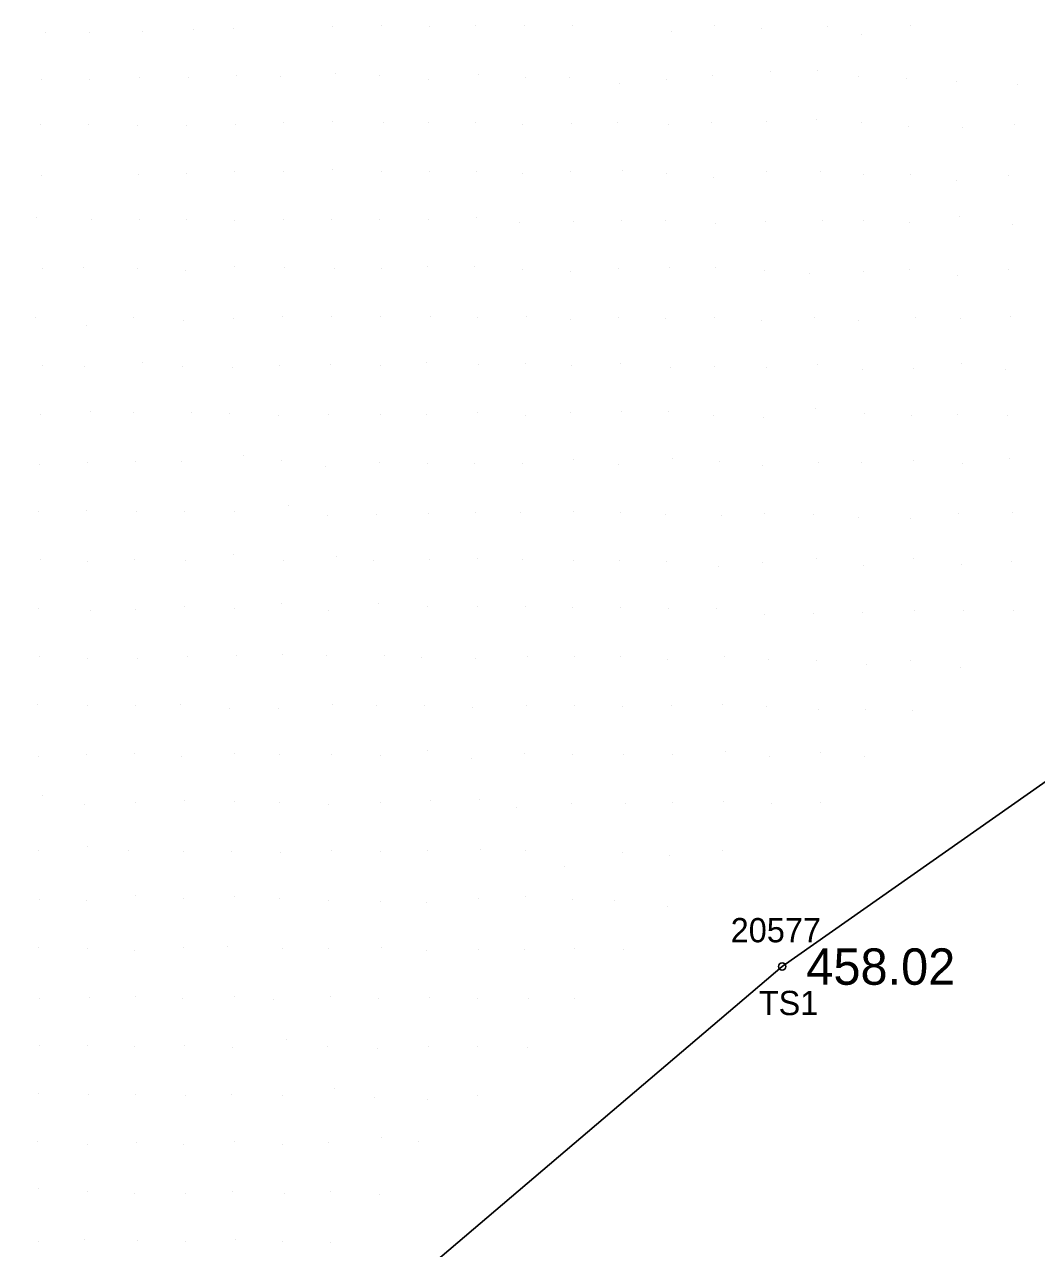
# Model space of a CAD drawing. Extents: x 1747760 to 1751131, y 649333 to 653784.
# Drawn here: x 1749239.9 to 1749281.6, y 651279.3 to 651329.8 of the extents above; entities that cross this region are included whole.
import ezdxf

# ---------------------------------------------------------------- set-up
doc = ezdxf.new("R2010")
doc.units = 0
for name, color, linetype in [('RD_DTM_BkLn2', 7, 'Continuous'), ('RD_DTM_BkLn_txCode', 7, 'Continuous'), ('RD_DTM_Spot', 7, 'Continuous'), ('RD_EX_TX_Misc_ELEV', 7, 'Continuous'), ('RD_SMD_Locator', 7, 'Continuous')]:
    doc.layers.add(name, color=color, linetype=linetype)

msp = doc.modelspace()

# ---------------------------------------------------------------- linework, layer by layer
at = {"layer": 'RD_DTM_BkLn2'}
msp.add_lwpolyline([(1749334.274, 651347.939), (1749311.737, 651326.42), (1749292.613, 651306.019), (1749271.131, 651290.935), (1749254.537, 651276.811), (1749242.73, 651265.483), (1749232.71, 651251.743), (1749211.561, 651228.743), (1749190.496, 651216.053), (1749178.766, 651203.369)], dxfattribs=at)
at = {"layer": 'RD_DTM_Spot'}
for p, q in [((1749240.766, 651329.413), (1749240.766, 651329.413)), ((1749242.609, 651329.431), (1749242.609, 651329.431)), ((1749244.794, 651329.464), (1749244.794, 651329.464)), ((1749246.872, 651329.565), (1749246.872, 651329.565)), ((1749248.519, 651329.588), (1749248.519, 651329.588)), ((1749252.618, 651329.682), (1749252.618, 651329.682)), ((1749254.619, 651329.723), (1749254.619, 651329.723)), ((1749256.621, 651329.689), (1749256.621, 651329.689)), ((1749258.503, 651329.72), (1749258.503, 651329.72)), ((1749260.497, 651329.72), (1749260.497, 651329.72)), ((1749262.483, 651329.693), (1749262.483, 651329.693)), ((1749266.57, 651329.475), (1749266.57, 651329.475)), ((1749268.354, 651329.698), (1749268.354, 651329.698)), ((1749270.294, 651329.598), (1749270.294, 651329.598)), ((1749272.982, 651329.689), (1749272.982, 651329.689)), ((1749274.385, 651329.34), (1749274.385, 651329.34)), ((1749276.403, 651329.729), (1749276.403, 651329.729)), ((1749270.671, 651327.81), (1749270.671, 651327.81)), ((1749272.605, 651327.87), (1749272.605, 651327.87)), ((1749240.602, 651327.495), (1749240.602, 651327.495)), ((1749242.58, 651327.499), (1749242.58, 651327.499)), ((1749244.656, 651327.566), (1749244.656, 651327.566)), ((1749246.659, 651327.567), (1749246.659, 651327.567)), ((1749248.641, 651327.67), (1749248.641, 651327.67)), ((1749250.449, 651327.615), (1749250.449, 651327.615)), ((1749252.719, 651327.722), (1749252.719, 651327.722)), ((1749254.526, 651327.647), (1749254.526, 651327.647)), ((1749256.543, 651327.488), (1749256.543, 651327.488)), ((1749258.629, 651327.674), (1749258.629, 651327.674)), ((1749260.576, 651327.551), (1749260.576, 651327.551)), ((1749262.355, 651327.585), (1749262.355, 651327.585)), ((1749264.438, 651327.329), (1749264.438, 651327.329)), ((1749266.363, 651327.489), (1749266.363, 651327.489)), ((1749268.274, 651327.663), (1749268.274, 651327.663)), ((1749274.26, 651327.61), (1749274.26, 651327.61)), ((1749276.263, 651327.527), (1749276.263, 651327.527)), ((1749278.316, 651327.392), (1749278.316, 651327.392)), ((1749280.846, 651327.27), (1749280.846, 651327.27)), ((1749272.541, 651325.844), (1749272.541, 651325.844)), ((1749240.562, 651325.637), (1749240.562, 651325.637)), ((1749242.548, 651325.621), (1749242.548, 651325.621)), ((1749244.556, 651325.61), (1749244.556, 651325.61)), ((1749246.572, 651325.599), (1749246.572, 651325.599)), ((1749248.597, 651325.652), (1749248.597, 651325.652)), ((1749250.574, 651325.699), (1749250.574, 651325.699)), ((1749252.592, 651325.768), (1749252.592, 651325.768)), ((1749254.706, 651325.723), (1749254.706, 651325.723)), ((1749256.564, 651325.721), (1749256.564, 651325.721)), ((1749258.508, 651325.718), (1749258.508, 651325.718)), ((1749260.428, 651325.646), (1749260.428, 651325.646)), ((1749262.458, 651325.678), (1749262.458, 651325.678)), ((1749264.338, 651325.709), (1749264.338, 651325.709)), ((1749266.43, 651325.651), (1749266.43, 651325.651)), ((1749268.219, 651325.729), (1749268.219, 651325.729)), ((1749270.497, 651325.769), (1749270.497, 651325.769)), ((1749274.394, 651325.717), (1749274.394, 651325.717)), ((1749276.338, 651325.557), (1749276.338, 651325.557)), ((1749278.566, 651325.527), (1749278.566, 651325.527)), ((1749280.727, 651325.625), (1749280.727, 651325.625)), ((1749252.606, 651323.773), (1749252.606, 651323.773)), ((1749240.626, 651323.519), (1749240.626, 651323.519)), ((1749244.602, 651323.587), (1749244.602, 651323.587)), ((1749246.601, 651323.595), (1749246.601, 651323.595)), ((1749248.581, 651323.68), (1749248.581, 651323.68)), ((1749250.587, 651323.713), (1749250.587, 651323.713)), ((1749254.608, 651323.712), (1749254.608, 651323.712)), ((1749256.604, 651323.678), (1749256.604, 651323.678)), ((1749258.531, 651323.677), (1749258.531, 651323.677)), ((1749260.439, 651323.609), (1749260.439, 651323.609)), ((1749262.406, 651323.688), (1749262.406, 651323.688)), ((1749264.575, 651323.756), (1749264.575, 651323.756)), ((1749266.376, 651323.596), (1749266.376, 651323.596)), ((1749268.302, 651323.45), (1749268.302, 651323.45)), ((1749270.487, 651323.704), (1749270.487, 651323.704)), ((1749272.727, 651323.695), (1749272.727, 651323.695)), ((1749274.499, 651323.573), (1749274.499, 651323.573)), ((1749276.429, 651323.591), (1749276.429, 651323.591)), ((1749278.321, 651323.307), (1749278.321, 651323.307)), ((1749280.453, 651323.546), (1749280.453, 651323.546)), ((1749240.397, 651321.808), (1749240.397, 651321.808)), ((1749258.531, 651321.803), (1749258.531, 651321.803)), ((1749278.439, 651321.853), (1749278.439, 651321.853)), ((1749242.686, 651321.703), (1749242.686, 651321.703)), ((1749244.642, 651321.707), (1749244.642, 651321.707)), ((1749246.604, 651321.72), (1749246.604, 651321.72)), ((1749248.569, 651321.683), (1749248.569, 651321.683)), ((1749250.567, 651321.708), (1749250.567, 651321.708)), ((1749252.582, 651321.699), (1749252.582, 651321.699)), ((1749254.531, 651321.733), (1749254.531, 651321.733)), ((1749256.579, 651321.727), (1749256.579, 651321.727)), ((1749260.31, 651321.613), (1749260.31, 651321.613)), ((1749262.516, 651321.619), (1749262.516, 651321.619)), ((1749264.526, 651321.667), (1749264.526, 651321.667)), ((1749266.33, 651321.684), (1749266.33, 651321.684)), ((1749268.403, 651321.569), (1749268.403, 651321.569)), ((1749270.431, 651321.639), (1749270.431, 651321.639)), ((1749272.786, 651321.673), (1749272.786, 651321.673)), ((1749274.486, 651321.681), (1749274.486, 651321.681)), ((1749276.388, 651321.614), (1749276.388, 651321.614)), ((1749280.627, 651321.51), (1749280.627, 651321.51)), ((1749242.358, 651319.728), (1749242.358, 651319.728)), ((1749248.565, 651319.764), (1749248.565, 651319.764)), ((1749250.612, 651319.752), (1749250.612, 651319.752)), ((1749256.529, 651319.791), (1749256.529, 651319.791)), ((1749258.466, 651319.787), (1749258.466, 651319.787)), ((1749240.64, 651319.706), (1749240.64, 651319.706)), ((1749244.557, 651319.688), (1749244.557, 651319.688)), ((1749246.548, 651319.634), (1749246.548, 651319.634)), ((1749252.668, 651319.681), (1749252.668, 651319.681)), ((1749254.637, 651319.683), (1749254.637, 651319.683)), ((1749260.428, 651319.663), (1749260.428, 651319.663)), ((1749262.4, 651319.591), (1749262.4, 651319.591)), ((1749264.392, 651319.699), (1749264.392, 651319.699)), ((1749266.491, 651319.722), (1749266.491, 651319.722)), ((1749268.372, 651319.727), (1749268.372, 651319.727)), ((1749270.4, 651319.613), (1749270.4, 651319.613)), ((1749272.261, 651319.493), (1749272.261, 651319.493)), ((1749274.49, 651319.564), (1749274.49, 651319.564)), ((1749276.375, 651319.647), (1749276.375, 651319.647)), ((1749278.35, 651319.432), (1749278.35, 651319.432)), ((1749280.469, 651319.661), (1749280.469, 651319.661)), ((1749252.557, 651317.736), (1749252.557, 651317.736)), ((1749254.592, 651317.723), (1749254.592, 651317.723)), ((1749260.611, 651317.715), (1749260.611, 651317.715)), ((1749240.356, 651317.687), (1749240.356, 651317.687)), ((1749242.464, 651317.346), (1749242.464, 651317.346)), ((1749244.399, 651317.69), (1749244.399, 651317.69)), ((1749246.475, 651317.553), (1749246.475, 651317.553)), ((1749248.528, 651317.622), (1749248.528, 651317.622)), ((1749250.527, 651317.709), (1749250.527, 651317.709)), ((1749256.629, 651317.705), (1749256.629, 651317.705)), ((1749258.566, 651317.676), (1749258.566, 651317.676)), ((1749262.404, 651317.615), (1749262.404, 651317.615)), ((1749264.398, 651317.696), (1749264.398, 651317.696)), ((1749266.337, 651317.652), (1749266.337, 651317.652)), ((1749268.349, 651317.688), (1749268.349, 651317.688)), ((1749270.281, 651317.571), (1749270.281, 651317.571)), ((1749272.446, 651317.661), (1749272.446, 651317.661)), ((1749274.275, 651317.563), (1749274.275, 651317.563)), ((1749276.646, 651317.662), (1749276.646, 651317.662)), ((1749278.477, 651317.626), (1749278.477, 651317.626)), ((1749280.557, 651317.703), (1749280.557, 651317.703)), ((1749240.66, 651315.712), (1749240.66, 651315.712)), ((1749244.792, 651315.827), (1749244.792, 651315.827)), ((1749250.44, 651315.698), (1749250.44, 651315.698)), ((1749252.512, 651315.744), (1749252.512, 651315.744)), ((1749254.577, 651315.696), (1749254.577, 651315.696)), ((1749256.484, 651315.811), (1749256.484, 651315.811)), ((1749258.639, 651315.732), (1749258.639, 651315.732)), ((1749260.574, 651315.786), (1749260.574, 651315.786)), ((1749262.445, 651315.71), (1749262.445, 651315.71)), ((1749264.453, 651315.769), (1749264.453, 651315.769)), ((1749272.573, 651315.76), (1749272.573, 651315.76)), ((1749278.524, 651315.8), (1749278.524, 651315.8)), ((1749242.374, 651315.681), (1749242.374, 651315.681)), ((1749246.408, 651315.659), (1749246.408, 651315.659)), ((1749248.492, 651315.615), (1749248.492, 651315.615)), ((1749266.549, 651315.604), (1749266.549, 651315.604)), ((1749268.332, 651315.68), (1749268.332, 651315.68)), ((1749270.468, 651315.641), (1749270.468, 651315.641)), ((1749274.457, 651315.557), (1749274.457, 651315.557)), ((1749276.527, 651315.581), (1749276.527, 651315.581)), ((1749280.356, 651315.531), (1749280.356, 651315.531)), ((1749240.565, 651313.692), (1749240.565, 651313.692)), ((1749242.652, 651313.799), (1749242.652, 651313.799)), ((1749244.401, 651313.766), (1749244.401, 651313.766)), ((1749246.814, 651313.783), (1749246.814, 651313.783)), ((1749248.381, 651313.725), (1749248.381, 651313.725)), ((1749254.599, 651313.697), (1749254.599, 651313.697)), ((1749258.583, 651313.748), (1749258.583, 651313.748)), ((1749262.43, 651313.749), (1749262.43, 651313.749)), ((1749264.499, 651313.8), (1749264.499, 651313.8)), ((1749266.43, 651313.804), (1749266.43, 651313.804)), ((1749272.508, 651313.927), (1749272.508, 651313.927)), ((1749274.526, 651313.722), (1749274.526, 651313.722)), ((1749278.346, 651313.699), (1749278.346, 651313.699)), ((1749250.385, 651313.637), (1749250.385, 651313.637)), ((1749252.445, 651313.669), (1749252.445, 651313.669)), ((1749256.483, 651313.673), (1749256.483, 651313.673)), ((1749260.577, 651313.633), (1749260.577, 651313.633)), ((1749268.305, 651313.637), (1749268.305, 651313.637)), ((1749270.373, 651313.567), (1749270.373, 651313.567)), ((1749276.457, 651313.646), (1749276.457, 651313.646)), ((1749280.4, 651313.628), (1749280.4, 651313.628)), ((1749242.5, 651311.721), (1749242.5, 651311.721)), ((1749244.479, 651311.734), (1749244.479, 651311.734)), ((1749246.379, 651311.757), (1749246.379, 651311.757)), ((1749248.941, 651311.981), (1749248.941, 651311.981)), ((1749250.487, 651311.782), (1749250.487, 651311.782)), ((1749254.532, 651311.718), (1749254.532, 651311.718)), ((1749256.502, 651311.668), (1749256.502, 651311.668)), ((1749258.445, 651311.661), (1749258.445, 651311.661)), ((1749262.536, 651311.811), (1749262.536, 651311.811)), ((1749266.617, 651311.867), (1749266.617, 651311.867)), ((1749268.568, 651311.765), (1749268.568, 651311.765)), ((1749272.621, 651311.713), (1749272.621, 651311.713)), ((1749274.421, 651311.703), (1749274.421, 651311.703)), ((1749276.549, 651311.788), (1749276.549, 651311.788)), ((1749278.548, 651311.667), (1749278.548, 651311.667)), ((1749280.515, 651311.851), (1749280.515, 651311.851)), ((1749240.514, 651311.634), (1749240.514, 651311.634)), ((1749252.316, 651311.554), (1749252.316, 651311.554)), ((1749260.454, 651311.645), (1749260.454, 651311.645)), ((1749264.391, 651311.643), (1749264.391, 651311.643)), ((1749270.305, 651311.584), (1749270.305, 651311.584)), ((1749240.472, 651309.675), (1749240.472, 651309.675)), ((1749242.471, 651309.709), (1749242.471, 651309.709)), ((1749244.509, 651309.675), (1749244.509, 651309.675)), ((1749246.521, 651309.705), (1749246.521, 651309.705)), ((1749248.562, 651309.688), (1749248.562, 651309.688)), ((1749250.788, 651309.921), (1749250.788, 651309.921)), ((1749258.511, 651309.66), (1749258.511, 651309.66)), ((1749262.523, 651309.677), (1749262.523, 651309.677)), ((1749264.49, 651309.643), (1749264.49, 651309.643)), ((1749280.63, 651309.659), (1749280.63, 651309.659)), ((1749252.407, 651309.538), (1749252.407, 651309.538)), ((1749254.409, 651309.578), (1749254.409, 651309.578)), ((1749256.56, 651309.619), (1749256.56, 651309.619)), ((1749260.354, 651309.629), (1749260.354, 651309.629)), ((1749266.318, 651309.573), (1749266.318, 651309.573)), ((1749268.623, 651309.525), (1749268.623, 651309.525)), ((1749270.387, 651309.608), (1749270.387, 651309.608)), ((1749272.431, 651309.572), (1749272.431, 651309.572)), ((1749274.272, 651309.431), (1749274.272, 651309.431)), ((1749276.437, 651309.403), (1749276.437, 651309.403)), ((1749278.408, 651309.588), (1749278.408, 651309.588)), ((1749240.559, 651307.713), (1749240.559, 651307.713)), ((1749242.527, 651307.641), (1749242.527, 651307.641)), ((1749244.441, 651307.716), (1749244.441, 651307.716)), ((1749246.528, 651307.655), (1749246.528, 651307.655)), ((1749248.534, 651307.907), (1749248.534, 651307.907)), ((1749250.594, 651307.656), (1749250.594, 651307.656)), ((1749252.755, 651307.822), (1749252.755, 651307.822)), ((1749254.285, 651307.674), (1749254.285, 651307.674)), ((1749256.593, 651307.691), (1749256.593, 651307.691)), ((1749258.564, 651307.732), (1749258.564, 651307.732)), ((1749260.435, 651307.703), (1749260.435, 651307.703)), ((1749262.54, 651307.667), (1749262.54, 651307.667)), ((1749264.411, 651307.68), (1749264.411, 651307.68)), ((1749266.351, 651307.634), (1749266.351, 651307.634)), ((1749272.537, 651307.745), (1749272.537, 651307.745)), ((1749276.533, 651307.756), (1749276.533, 651307.756)), ((1749280.574, 651307.631), (1749280.574, 651307.631)), ((1749268.493, 651307.44), (1749268.493, 651307.44)), ((1749270.327, 651307.569), (1749270.327, 651307.569)), ((1749274.5, 651307.445), (1749274.5, 651307.445)), ((1749278.54, 651307.509), (1749278.54, 651307.509)), ((1749240.483, 651305.699), (1749240.483, 651305.699)), ((1749244.5, 651305.652), (1749244.5, 651305.652)), ((1749246.524, 651305.759), (1749246.524, 651305.759)), ((1749248.566, 651305.679), (1749248.566, 651305.679)), ((1749250.524, 651305.888), (1749250.524, 651305.888)), ((1749252.459, 651305.627), (1749252.459, 651305.627)), ((1749254.499, 651305.876), (1749254.499, 651305.876)), ((1749256.503, 651305.752), (1749256.503, 651305.752)), ((1749258.563, 651305.772), (1749258.563, 651305.772)), ((1749260.558, 651305.778), (1749260.558, 651305.778)), ((1749262.486, 651305.75), (1749262.486, 651305.75)), ((1749264.474, 651305.729), (1749264.474, 651305.729)), ((1749266.454, 651305.674), (1749266.454, 651305.674)), ((1749268.425, 651305.69), (1749268.425, 651305.69)), ((1749276.585, 651305.616), (1749276.585, 651305.616)), ((1749278.61, 651305.607), (1749278.61, 651305.607)), ((1749280.682, 651305.625), (1749280.682, 651305.625)), ((1749242.636, 651305.603), (1749242.636, 651305.603)), ((1749270.395, 651305.456), (1749270.395, 651305.456)), ((1749272.445, 651305.497), (1749272.445, 651305.497)), ((1749274.459, 651305.514), (1749274.459, 651305.514)), ((1749240.549, 651303.702), (1749240.549, 651303.702)), ((1749242.497, 651303.635), (1749242.497, 651303.635)), ((1749244.557, 651303.641), (1749244.557, 651303.641)), ((1749246.616, 651303.718), (1749246.616, 651303.718)), ((1749248.631, 651303.765), (1749248.631, 651303.765)), ((1749250.538, 651303.795), (1749250.538, 651303.795)), ((1749252.378, 651303.758), (1749252.378, 651303.758)), ((1749254.728, 651303.742), (1749254.728, 651303.742)), ((1749256.293, 651303.656), (1749256.293, 651303.656)), ((1749258.484, 651303.643), (1749258.484, 651303.643)), ((1749260.642, 651303.696), (1749260.642, 651303.696)), ((1749262.58, 651303.708), (1749262.58, 651303.708)), ((1749264.452, 651303.73), (1749264.452, 651303.73)), ((1749266.396, 651303.6), (1749266.396, 651303.6)), ((1749268.768, 651303.7), (1749268.768, 651303.7)), ((1749270.573, 651303.592), (1749270.573, 651303.592)), ((1749272.549, 651303.562), (1749272.549, 651303.562)), ((1749274.609, 651303.381), (1749274.609, 651303.381)), ((1749276.424, 651303.547), (1749276.424, 651303.547)), ((1749278.481, 651303.24), (1749278.481, 651303.24)), ((1749240.469, 651301.749), (1749240.469, 651301.749)), ((1749242.511, 651301.707), (1749242.511, 651301.707)), ((1749244.493, 651301.701), (1749244.493, 651301.701)), ((1749246.338, 651301.727), (1749246.338, 651301.727)), ((1749250.369, 651301.586), (1749250.369, 651301.586)), ((1749252.614, 651301.748), (1749252.614, 651301.748)), ((1749254.407, 651301.712), (1749254.407, 651301.712)), ((1749256.402, 651301.7), (1749256.402, 651301.7)), ((1749258.388, 651301.625), (1749258.388, 651301.625)), ((1749260.585, 651301.71), (1749260.585, 651301.71)), ((1749262.569, 651301.712), (1749262.569, 651301.712)), ((1749264.565, 651301.653), (1749264.565, 651301.653)), ((1749266.555, 651301.711), (1749266.555, 651301.711)), ((1749268.656, 651301.751), (1749268.656, 651301.751)), ((1749270.482, 651301.661), (1749270.482, 651301.661)), ((1749248.38, 651301.562), (1749248.38, 651301.562)), ((1749272.637, 651301.547), (1749272.637, 651301.547)), ((1749274.561, 651301.54), (1749274.561, 651301.54)), ((1749276.484, 651301.471), (1749276.484, 651301.471)), ((1749240.486, 651299.601), (1749240.486, 651299.601)), ((1749242.487, 651299.667), (1749242.487, 651299.667)), ((1749244.451, 651299.726), (1749244.451, 651299.726)), ((1749246.401, 651299.592), (1749246.401, 651299.592)), ((1749248.551, 651299.712), (1749248.551, 651299.712)), ((1749250.435, 651299.685), (1749250.435, 651299.685)), ((1749252.569, 651299.654), (1749252.569, 651299.654)), ((1749254.595, 651299.642), (1749254.595, 651299.642)), ((1749256.538, 651299.84), (1749256.538, 651299.84)), ((1749260.509, 651299.696), (1749260.509, 651299.696)), ((1749262.481, 651299.691), (1749262.481, 651299.691)), ((1749264.595, 651299.69), (1749264.595, 651299.69)), ((1749266.614, 651299.677), (1749266.614, 651299.677)), ((1749268.785, 651299.818), (1749268.785, 651299.818)), ((1749270.605, 651299.597), (1749270.605, 651299.597)), ((1749272.724, 651299.741), (1749272.724, 651299.741)), ((1749274.543, 651299.577), (1749274.543, 651299.577)), ((1749258.343, 651299.527), (1749258.343, 651299.527)), ((1749240.659, 651297.972), (1749240.659, 651297.972)), ((1749242.38, 651297.626), (1749242.38, 651297.626)), ((1749244.472, 651297.698), (1749244.472, 651297.698)), ((1749246.5, 651297.78), (1749246.5, 651297.78)), ((1749248.577, 651297.752), (1749248.577, 651297.752)), ((1749250.442, 651297.691), (1749250.442, 651297.691)), ((1749252.444, 651297.61), (1749252.444, 651297.61)), ((1749254.602, 651297.711), (1749254.602, 651297.711)), ((1749256.649, 651297.767), (1749256.649, 651297.767)), ((1749258.661, 651297.822), (1749258.661, 651297.822)), ((1749262.456, 651297.654), (1749262.456, 651297.654)), ((1749264.677, 651297.649), (1749264.677, 651297.649)), ((1749266.627, 651297.704), (1749266.627, 651297.704)), ((1749268.724, 651297.748), (1749268.724, 651297.748)), ((1749270.709, 651297.643), (1749270.709, 651297.643)), ((1749272.719, 651297.694), (1749272.719, 651297.694)), ((1749260.18, 651297.49), (1749260.18, 651297.49)), ((1749240.485, 651295.706), (1749240.485, 651295.706)), ((1749242.511, 651295.863), (1749242.511, 651295.863)), ((1749244.209, 651295.701), (1749244.209, 651295.701)), ((1749246.481, 651295.69), (1749246.481, 651295.69)), ((1749248.436, 651295.666), (1749248.436, 651295.666)), ((1749250.463, 651295.618), (1749250.463, 651295.618)), ((1749252.546, 651295.71), (1749252.546, 651295.71)), ((1749254.595, 651295.679), (1749254.595, 651295.679)), ((1749256.509, 651295.709), (1749256.509, 651295.709)), ((1749258.697, 651295.764), (1749258.697, 651295.764)), ((1749260.54, 651295.722), (1749260.54, 651295.722)), ((1749264.562, 651295.633), (1749264.562, 651295.633)), ((1749268.679, 651295.698), (1749268.679, 651295.698)), ((1749262.147, 651295.043), (1749262.147, 651295.043)), ((1749266.502, 651295.495), (1749266.502, 651295.495)), ((1749240.541, 651293.707), (1749240.541, 651293.707)), ((1749242.461, 651293.661), (1749242.461, 651293.661)), ((1749244.507, 651293.879), (1749244.507, 651293.879)), ((1749246.464, 651293.721), (1749246.464, 651293.721)), ((1749248.577, 651293.803), (1749248.577, 651293.803)), ((1749250.401, 651293.76), (1749250.401, 651293.76)), ((1749252.46, 651293.654), (1749252.46, 651293.654)), ((1749254.587, 651293.634), (1749254.587, 651293.634)), ((1749256.484, 651293.578), (1749256.484, 651293.578)), ((1749258.604, 651293.752), (1749258.604, 651293.752)), ((1749260.572, 651293.833), (1749260.572, 651293.833)), ((1749262.484, 651293.691), (1749262.484, 651293.691)), ((1749264.227, 651293.639), (1749264.227, 651293.639)), ((1749266.417, 651293.41), (1749266.417, 651293.41)), ((1749240.478, 651291.704), (1749240.478, 651291.704)), ((1749242.495, 651291.66), (1749242.495, 651291.66)), ((1749244.456, 651291.617), (1749244.456, 651291.617)), ((1749246.469, 651291.741), (1749246.469, 651291.741)), ((1749248.288, 651291.752), (1749248.288, 651291.752)), ((1749250.531, 651291.7), (1749250.531, 651291.7)), ((1749252.458, 651291.67), (1749252.458, 651291.67)), ((1749254.62, 651291.718), (1749254.62, 651291.718)), ((1749256.489, 651291.601), (1749256.489, 651291.601)), ((1749258.616, 651291.651), (1749258.616, 651291.651)), ((1749260.512, 651291.652), (1749260.512, 651291.652)), ((1749262.586, 651291.67), (1749262.586, 651291.67)), ((1749264.576, 651291.654), (1749264.576, 651291.654)), ((1749240.552, 651289.63), (1749240.552, 651289.63)), ((1749242.577, 651289.67), (1749242.577, 651289.67)), ((1749244.482, 651289.703), (1749244.482, 651289.703)), ((1749246.422, 651289.624), (1749246.422, 651289.624)), ((1749248.574, 651289.715), (1749248.574, 651289.715)), ((1749250.155, 651289.576), (1749250.155, 651289.576)), ((1749252.53, 651289.715), (1749252.53, 651289.715)), ((1749254.508, 651289.612), (1749254.508, 651289.612)), ((1749256.583, 651289.651), (1749256.583, 651289.651)), ((1749258.594, 651289.626), (1749258.594, 651289.626)), ((1749260.667, 651289.611), (1749260.667, 651289.611)), ((1749262.596, 651289.608), (1749262.596, 651289.608)), ((1749240.521, 651287.698), (1749240.521, 651287.698)), ((1749242.523, 651287.693), (1749242.523, 651287.693)), ((1749244.444, 651287.628), (1749244.444, 651287.628)), ((1749246.495, 651287.666), (1749246.495, 651287.666)), ((1749248.477, 651287.6), (1749248.477, 651287.6)), ((1749250.726, 651287.925), (1749250.726, 651287.925)), ((1749252.391, 651287.626), (1749252.391, 651287.626)), ((1749254.455, 651287.572), (1749254.455, 651287.572)), ((1749256.559, 651287.621), (1749256.559, 651287.621)), ((1749258.597, 651287.651), (1749258.597, 651287.651)), ((1749260.626, 651287.608), (1749260.626, 651287.608)), ((1749240.471, 651285.685), (1749240.471, 651285.685)), ((1749242.558, 651285.679), (1749242.558, 651285.679)), ((1749244.485, 651285.663), (1749244.485, 651285.663)), ((1749246.529, 651285.628), (1749246.529, 651285.628)), ((1749248.448, 651285.646), (1749248.448, 651285.646)), ((1749250.539, 651285.616), (1749250.539, 651285.616)), ((1749252.704, 651285.904), (1749252.704, 651285.904)), ((1749254.323, 651285.56), (1749254.323, 651285.56)), ((1749256.514, 651285.462), (1749256.514, 651285.462)), ((1749258.585, 651285.603), (1749258.585, 651285.603)), ((1749240.464, 651283.73), (1749240.464, 651283.73)), ((1749242.517, 651283.604), (1749242.517, 651283.604)), ((1749244.538, 651283.68), (1749244.538, 651283.68)), ((1749246.478, 651283.622), (1749246.478, 651283.622)), ((1749248.577, 651283.72), (1749248.577, 651283.72)), ((1749250.526, 651283.594), (1749250.526, 651283.594)), ((1749252.453, 651283.674), (1749252.453, 651283.674)), ((1749254.613, 651283.874), (1749254.613, 651283.874)), ((1749256.157, 651283.725), (1749256.157, 651283.725)), ((1749240.507, 651281.794), (1749240.507, 651281.794)), ((1749242.496, 651281.682), (1749242.496, 651281.682)), ((1749244.449, 651281.6), (1749244.449, 651281.6)), ((1749246.536, 651281.591), (1749246.536, 651281.591)), ((1749248.466, 651281.651), (1749248.466, 651281.651)), ((1749250.612, 651281.599), (1749250.612, 651281.599)), ((1749252.533, 651281.655), (1749252.533, 651281.655)), ((1749254.541, 651281.551), (1749254.541, 651281.551)), ((1749240.509, 651279.594), (1749240.509, 651279.594)), ((1749242.401, 651279.697), (1749242.401, 651279.697)), ((1749244.556, 651279.641), (1749244.556, 651279.641)), ((1749246.544, 651279.611), (1749246.544, 651279.611)), ((1749248.594, 651279.683), (1749248.594, 651279.683)), ((1749250.542, 651279.617), (1749250.542, 651279.617)), ((1749252.51, 651279.555), (1749252.51, 651279.555))]:
    msp.add_line(p, q, dxfattribs=at)
at = {"layer": 'RD_SMD_Locator'}
msp.add_circle((1749271.131, 651290.935), 0.15, dxfattribs=at)

# ---------------------------------------------------------------- texts
at = {"layer": 'RD_DTM_BkLn_txCode'}
for s, p in [('20577', (1749269.013, 651291.935)), ('TS1', (1749270.171, 651288.935))]:
    msp.add_text(s, height=1, dxfattribs=at).set_placement(p)
at = {"layer": 'RD_EX_TX_Misc_ELEV'}
msp.add_text('458.02', height=1.5, dxfattribs=at).set_placement((1749272.131, 651290.185))

doc.saveas('drawing.dxf')
